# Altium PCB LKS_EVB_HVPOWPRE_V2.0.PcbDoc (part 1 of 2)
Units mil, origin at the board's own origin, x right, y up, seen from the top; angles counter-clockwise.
Board outline 6702.91 x 4340.71 mil, 2 copper layers (Top Layer, Bottom Layer); 149 components, 99 nets, 418 pads, 120 vias.
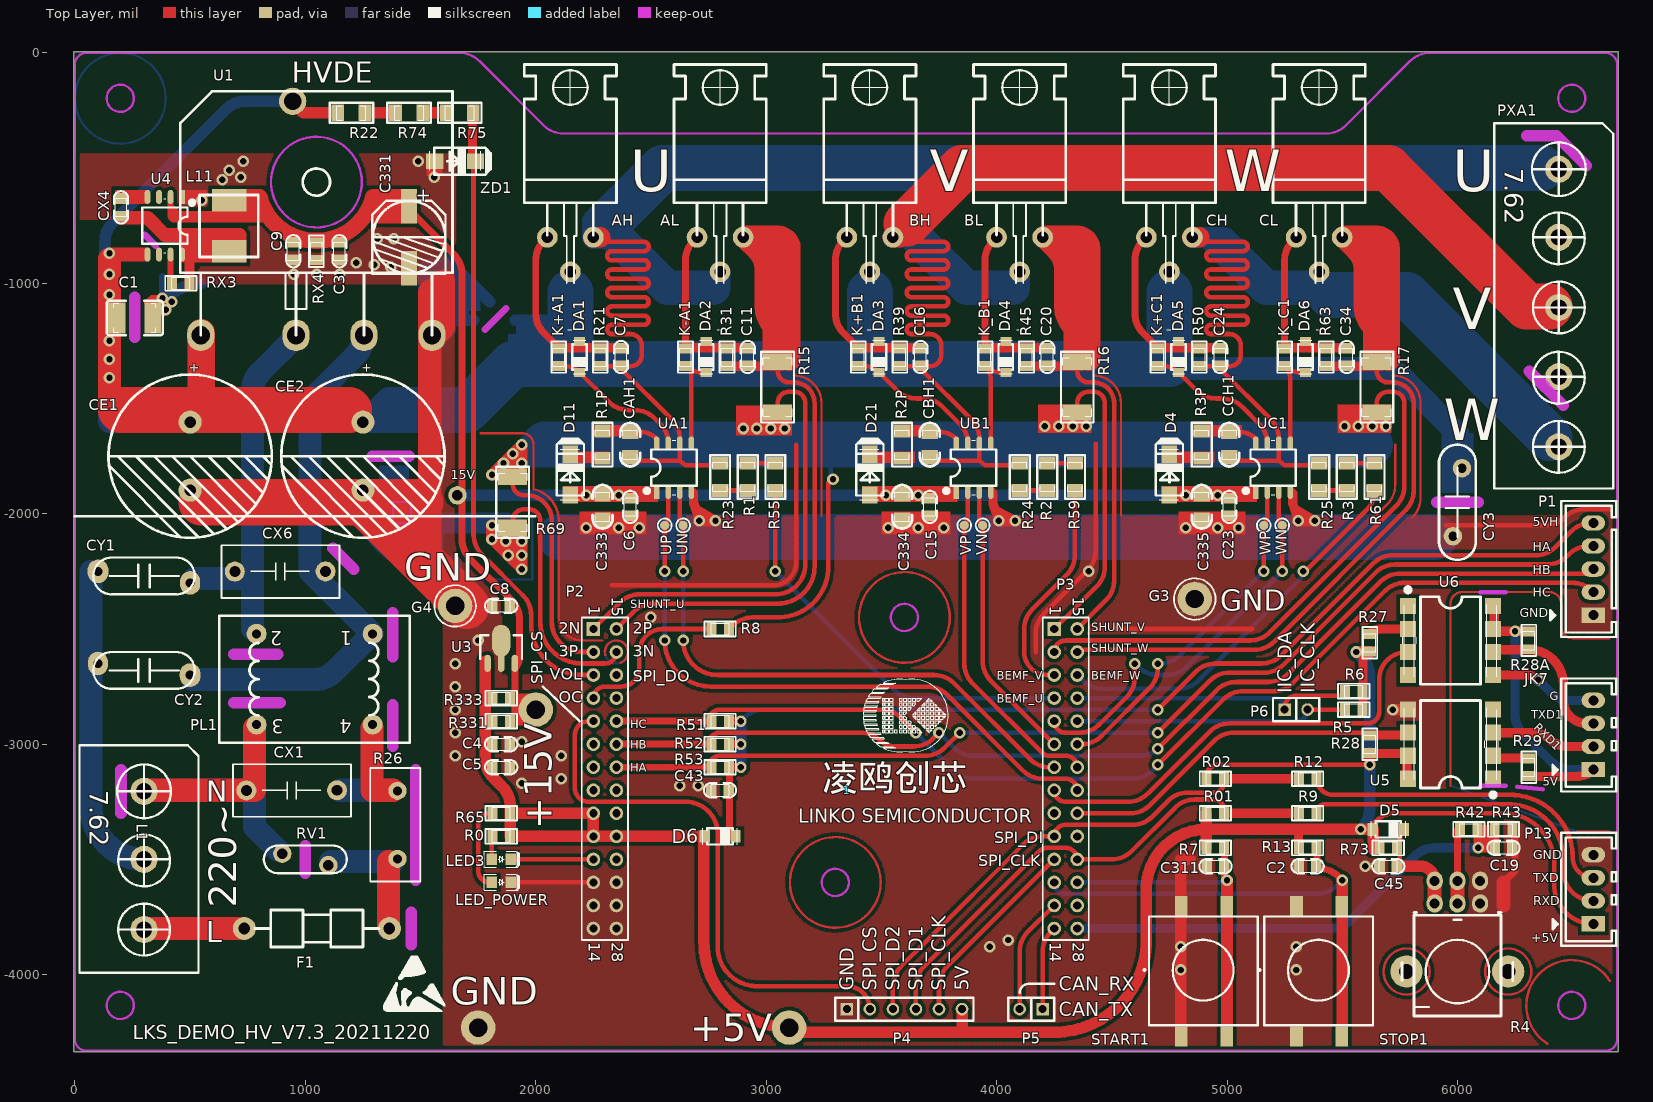
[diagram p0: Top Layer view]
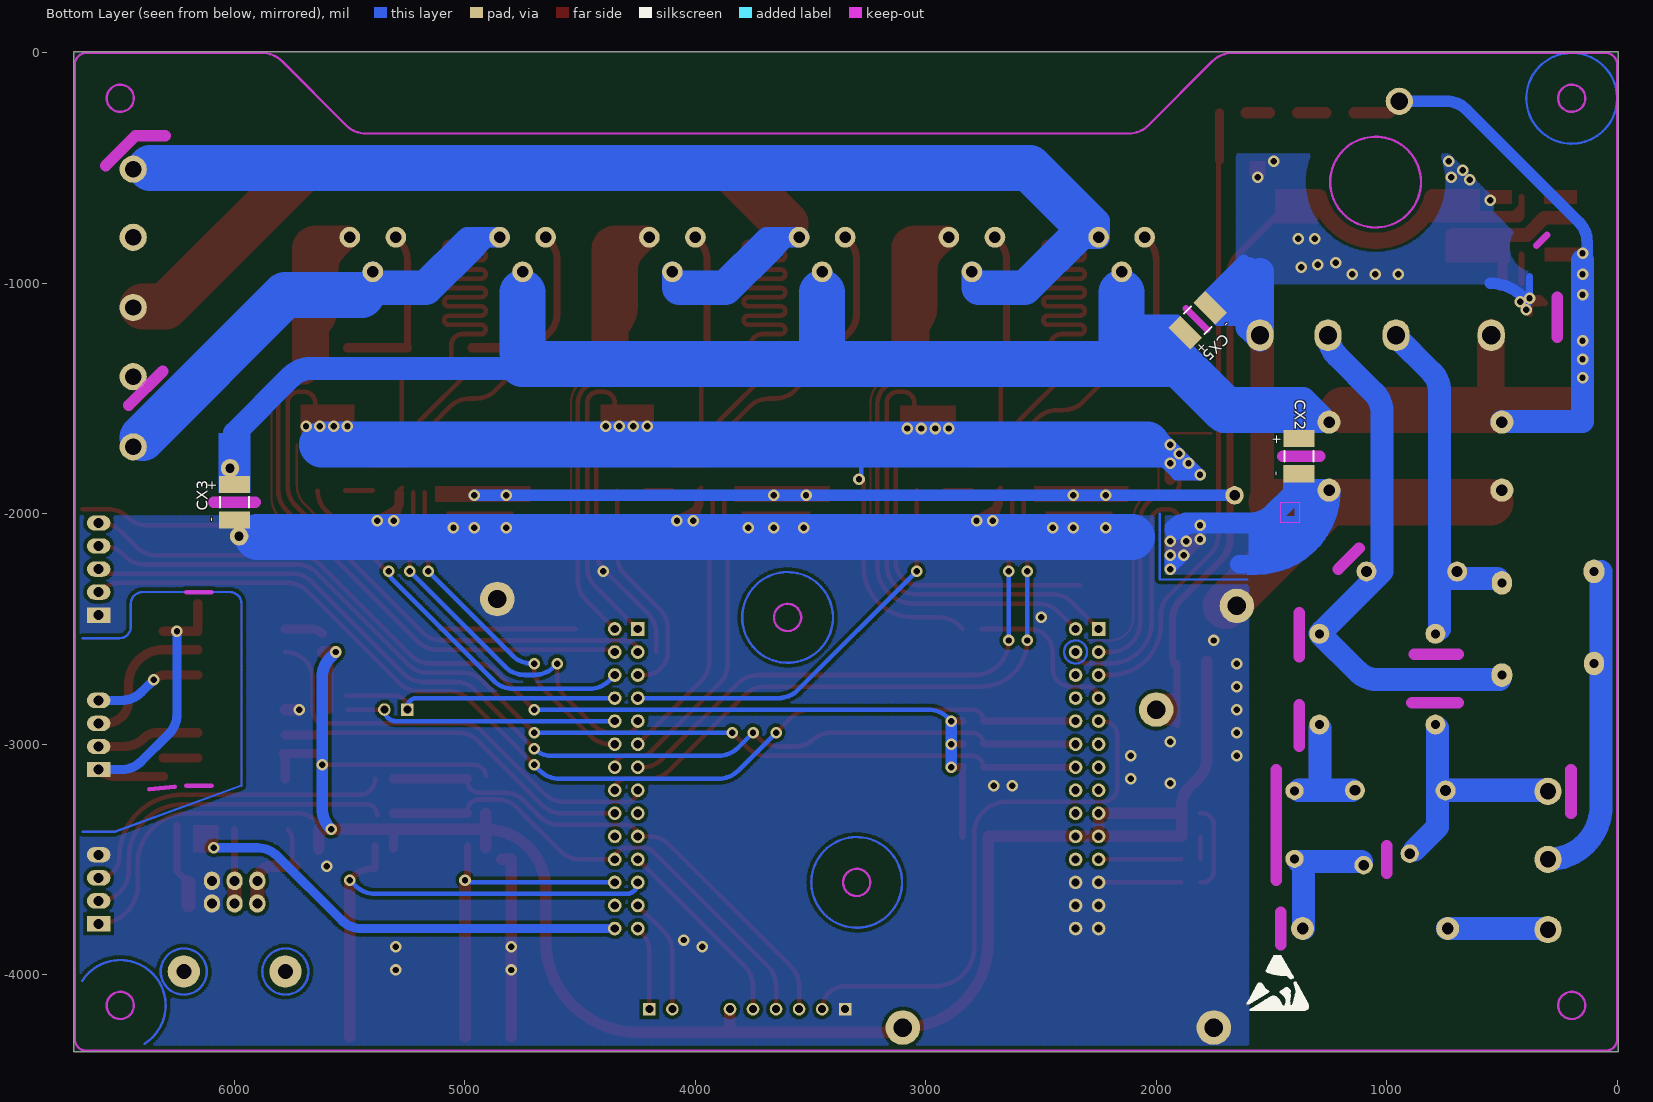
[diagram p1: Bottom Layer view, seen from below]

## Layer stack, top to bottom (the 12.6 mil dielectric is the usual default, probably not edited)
Top Solder: solder mask 0.4, Solder Resist, Dk 3.5
Top Layer: signal copper 1.4
Dielectric1: dielectric 12.6, FR-4, Dk 4.8
Bottom Layer: signal copper 1.4
Bottom Solder: solder mask 0.4, Solder Resist, Dk 3.5

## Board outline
-5,-4335.71 6697.91,-4335.71 6697.91,5 -5,5

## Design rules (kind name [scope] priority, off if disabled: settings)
AssemblyTestPointUsage [All] p0: scope1count=1 scope1_0_kind=Board scope1_0_value=Board scope2count=1 scope2_0_kind=Board scope2_0_value=Board commentlength=0
AssemblyTestpoint [All] p0: scope1count=1 scope1_0_kind=Board scope1_0_value=Board scope2count=1 scope2_0_kind=Board scope2_0_value=Board commentlength=0
Clearance HV铺铜 [All] p0 off: scope1count=1 scope1_0_kind=Board scope1_0_value=Board scope2count=1 scope2_0_kind=Board scope2_0_value=Board commentlength=0 gap=10
Clearance [All] p0 off: scope1count=1 scope1_0_kind=Board scope1_0_value=Board scope2count=1 scope2_0_kind=Board scope2_0_value=Board commentlength=0 gap=10
Clearance 铺铜 [All] p0: scope1count=1 scope1_0_kind=Board scope1_0_value=Board scope2count=1 scope2_0_kind=Board scope2_0_value=Board commentlength=0 gap=15
Clearance 铺铜 [All] p1: gap=15 ignorepadtopadclearanceinfootprint=FALSE
Clearance [All] p2 off: gap=10 ignorepadtopadclearanceinfootprint=FALSE
Clearance HV铺铜 [All] p3 off: gap=10 ignorepadtopadclearanceinfootprint=FALSE
ComponentClearance [All] p0 off: scope1count=1 scope1_0_kind=Board scope1_0_value=Board scope2count=1 scope2_0_kind=Board scope2_0_value=Board commentlength=0 gap=0 collisioncheckmode=3
ComponentClearance [All] p1 off: gap=0 collisioncheckmode=3 verticalgap=10 showdistances=FALSE
DiffPairsRouting [All] p0: scope1count=1 scope1_0_kind=Board scope1_0_value=Board scope2count=1 scope2_0_kind=Board scope2_0_value=Board commentlength=0
FabricationTestPointUsage TestPointUsage [All] p0: scope1count=1 scope1_0_kind=Board scope1_0_value=Board scope2count=1 scope2_0_kind=Board scope2_0_value=Board commentlength=0 valid=0 allowmultiple=FALSE
FabricationTestPointUsage TestPointUsage [All] p1: valid=0 allowmultiple=FALSE
FabricationTestpoint Testpoint [All] p0: scope1count=1 scope1_0_kind=Board scope1_0_value=Board scope2count=1 scope2_0_kind=Board scope2_0_value=Board commentlength=0 side=3 testpointundercomponent=TRUE minsize=40 maxsize=100 preferedsize=60 minholesize=20 maxholesize=40 preferedholesize=32 testpointgrid=1
FabricationTestpoint Testpoint [All] p1: side=3 testpointundercomponent=TRUE minsize=40 maxsize=100 preferedsize=60 minholesize=20 maxholesize=40 preferedholesize=32 testpointgrid=1 allowsidetop=TRUE allowsidebottom=TRUE usegrid=TRUE gridtolerance=0.01
FanoutControl Fanout_BGA [All] p0 off: scope1count=1 scope1_0_kind=Board scope1_0_value=Board scope2count=1 scope2_0_kind=Board scope2_0_value=Board commentlength=69 // Protel DXP Scope 1 Expression Was: IsBGA   Fanout_BGA (Default Rule)
FanoutControl Fanout_LCC [All] p0 off: scope1count=1 scope1_0_kind=Board scope1_0_value=Board scope2count=1 scope2_0_kind=Board scope2_0_value=Board commentlength=69 // Protel DXP Scope 1 Expression Was: IsLCC   Fanout_LCC (Default Rule)
FanoutControl Fanout_SOIC [All] p0 off: scope1count=1 scope1_0_kind=Board scope1_0_value=Board scope2count=1 scope2_0_kind=Board scope2_0_value=Board commentlength=71 // Protel DXP Scope 1 Expression Was: IsSOIC   Fanout_SOIC (Default Rule)
FanoutControl Fanout_Small [All] p0 off: scope1count=1 scope1_0_kind=Board scope1_0_value=Board scope2count=1 scope2_0_kind=Board scope2_0_value=Board commentlength=84 // Protel DXP Scope 1 Expression Was: (CompPinCount < 5)   Fanout_Small (Default Rule)
FanoutControl Fanout_Default [All] p0: scope1count=1 scope1_0_kind=Board scope1_0_value=Board scope2count=1 scope2_0_kind=Board scope2_0_value=Board commentlength=30 // Fanout_Default (Default Rule)
Height [All] p0: scope1count=1 scope1_0_kind=Board scope1_0_value=Board scope2count=1 scope2_0_kind=Board scope2_0_value=Board commentlength=0
HoleSize [All] p0: scope1count=1 scope1_0_kind=Board scope1_0_value=Board scope2count=1 scope2_0_kind=Board scope2_0_value=Board commentlength=0 absolutevalues=TRUE maxlimit=100 minlimit=1 maxpercent=80.000 minpercent=20.000
HoleToHoleClearance [All] p0: scope1count=1 scope1_0_kind=Board scope1_0_value=Board scope2count=1 scope2_0_kind=Board scope2_0_value=Board commentlength=0
LayerPairs [All] p0: scope1count=1 scope1_0_kind=Board scope1_0_value=Board scope2count=1 scope2_0_kind=Board scope2_0_value=Board commentlength=0 enforce=TRUE
MinimumSolderMaskSliver [All] p0: scope1count=1 scope1_0_kind=Board scope1_0_value=Board scope2count=1 scope2_0_kind=Board scope2_0_value=Board commentlength=0
NetAntennae [All] p0: scope1count=1 scope1_0_kind=Board scope1_0_value=Board scope2count=1 scope2_0_kind=Board scope2_0_value=Board commentlength=0
PasteMaskExpansion [All] p0: scope1count=1 scope1_0_kind=Board scope1_0_value=Board scope2count=1 scope2_0_kind=Board scope2_0_value=Board commentlength=0 expansion=0
PlaneClearance [All] p0: scope1count=1 scope1_0_kind=Board scope1_0_value=Board scope2count=1 scope2_0_kind=Board scope2_0_value=Board commentlength=0 clearance=20
PlaneConnect [All] p0: scope1count=1 scope1_0_kind=Board scope1_0_value=Board scope2count=1 scope2_0_kind=Board scope2_0_value=Board commentlength=0 planeconnectstyle=Relief reliefexpansion=20 reliefentries=4 reliefconductorwidth=10 reliefairgap=10
PolygonConnect [All] p0: scope1count=1 scope1_0_kind=Board scope1_0_value=Board scope2count=1 scope2_0_kind=Board scope2_0_value=Board commentlength=0 connectstyle=Direct reliefconductorwidth=30 reliefentries=4 polygonreliefangle="90 Angle"
PolygonConnect [All] p1: connectstyle=Direct reliefconductorwidth=30 reliefentries=4 polygonreliefangle="90 Angle" airgapwidth=10
RoutingCorners [All] p0: scope1count=1 scope1_0_kind=Board scope1_0_value=Board scope2count=1 scope2_0_kind=Board scope2_0_value=Board commentlength=0 cornerstyle=45-Degree minsetback=100 maxsetback=100
RoutingLayers [All] p0: scope1count=1 scope1_0_kind=Board scope1_0_value=Board scope2count=1 scope2_0_kind=Board scope2_0_value=Board commentlength=0 top layer=Horizontal bottom layer=Vertical
RoutingPriority [All] p0: scope1count=1 scope1_0_kind=Board scope1_0_value=Board scope2count=1 scope2_0_kind=Board scope2_0_value=Board commentlength=0
RoutingTopology [All] p0: scope1count=1 scope1_0_kind=Board scope1_0_value=Board scope2count=1 scope2_0_kind=Board scope2_0_value=Board commentlength=0 topology=Shortest
RoutingVias [All] p0: scope1count=1 scope1_0_kind=Board scope1_0_value=Board scope2count=1 scope2_0_kind=Board scope2_0_value=Board commentlength=0 holewidth=28 width=50 viastyle="Through Hole" minholewidth=28 minwidth=50 maxholewidth=28 maxwidth=50
RoutingVias [All] p1: holewidth=28 width=50 viastyle="Through Hole" minholewidth=28 minwidth=50 maxholewidth=28 maxwidth=50
ShortCircuit [All] p0: scope1count=1 scope1_0_kind=Board scope1_0_value=Board scope2count=1 scope2_0_kind=Board scope2_0_value=Board commentlength=0 allowed=FALSE
SilkToBoardRegionClearance [All] p0: scope1count=1 scope1_0_kind=Board scope1_0_value=Board scope2count=1 scope2_0_kind=Board scope2_0_value=Board commentlength=0
SilkToSilkClearance [All] p0: scope1count=1 scope1_0_kind=Board scope1_0_value=Board scope2count=1 scope2_0_kind=Board scope2_0_value=Board commentlength=0
SilkToSolderMaskClearance [All] p0 off: scope1count=1 scope1_0_kind=Board scope1_0_value=Board scope2count=1 scope2_0_kind=Board scope2_0_value=Board commentlength=44 // Protel DXP Scope 1 Expression Was: IsPad
SolderMaskExpansion [All] p0: scope1count=1 scope1_0_kind=Board scope1_0_value=Board scope2count=1 scope2_0_kind=Board scope2_0_value=Board commentlength=0 expansion=3
SolderMaskExpansion [All] p1: expansion=3 istentingtop=FALSE
UnRoutedNet [All] p0: scope1count=1 scope1_0_kind=Board scope1_0_value=Board scope2count=1 scope2_0_kind=Board scope2_0_value=Board commentlength=0
UnpouredPolygon [All] p0: scope1count=1 scope1_0_kind=Board scope1_0_value=Board scope2count=1 scope2_0_kind=Board scope2_0_value=Board commentlength=0
Width [All] p0: scope1count=1 scope1_0_kind=Board scope1_0_value=Board scope2count=1 scope2_0_kind=Board scope2_0_value=Board commentlength=0 maxlimit=300 minlimit=10 preferedwidth=40
Width [All] p1: maxlimit=300 minlimit=10 preferedwidth=40
27 further rules are at their usual default settings.

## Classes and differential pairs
component class LKS_HV_DEMO_081_V4.0: 0 C2 C3 C4 C5 C6 C7 C11 C15 C16 C19 C20 C23 C24 C34 C43 C45 C331 C333 CAH1 CBH1 CCH1 CE1 CE2 CX1 CX2 CX3 CX4 CY1 CY2 D1 D2 D4 D5 D6 D11 D21 DA1 DA2 DA3 DA4 DA5 DA6 F1 G3 G4 JK7 K+A1 K+B1 K+C1 K-A1 K-C1 K_B1 L1 L3 L11 LED1 LED2 LED3 LED_POWER P1 P2 P3 P13 P48V PL1 PXA1 R01 R1 R1P R2 R02 R2P R3 R3P R4 R9 R12 R13 R15 R16 R17 R21 R22 R23 R24 R25 R26 R27 R28 R29 R31 R39 R42 R43 R45 R50 R51 R52 R53 R55 R59 R61 R63 R65 R69 R73 R74 R75 R331 R333 RV1 RX3 RX4 START1 STOP1 U1 U3 U4 U5 U6 UA1 UB1 UC1 UN UP VAH1 VAL1 VBH1 VBL1 VCH1 VCL1 VN VP WN WP

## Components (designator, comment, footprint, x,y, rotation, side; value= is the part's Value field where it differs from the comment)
1 "LKS_sign" LKS_LOGO2 3350,-3200 r0 top
AH "XNF20N60T" TO220-3 2150,-800 r0 top
AL "XNF20N60T" TO220-3 2800,-800 r0 top
BH "XNF20N60T" TO220-3 3450,-800 r0 top
BL "XNF20N60T" TO220-3 4100,-800 r0 top
C1 "100nF/630V" 1812C(4532MM) 260,-1150 r0 top
C2 "100nF/50V" 0805C(2012MM) 5350,-3530 r0 top
C3 "100nF/25V" 0805C(2012MM) 1148.02,-860.53 r90 top
C4 "100nF/50V" 0805C(2012MM) 1850,-3000 r180 top
C5 "10uF/25V" 0805C(2012MM) 1850,-3100 r0 top
C6 "100nF/50V" 0805C(2012MM) 2410,-1970 r90 top
C7 "10nF/50V" 0805C(2012MM) 2370,-1320 r270 top
C8 "100nF/25V" 0805C(2012MM) 1850,-2400 r180 top
C9 "10uF/25V" 0805C(2012MM) 948.02,-860.53 r90 top
C11 "10nF/50V" 0805C(2012MM) 2920,-1320 r270 top
C15 "100nF/50V" 0805C(2012MM) 3710,-1970 r90 top
C16 "10nF/50V" 0805C(2012MM) 3670,-1320 r270 top
C19 "100nF/50V" 0805C(2012MM) 6200,-3450 r180 top
C20 "10nF/50V" 0805C(2012MM) 4220,-1320 r270 top
C23 "100nF/50V" 0805C(2012MM) 5010,-1970 r90 top
C24 "10nF/50V" 0805C(2012MM) 4970,-1320 r270 top
C34 "10nF/50V" 0805C(2012MM) 5520,-1320 r270 top
C43 "100nF/50V" 0805C(2012MM) 2800,-3200 r0 top
C45 "100nF/50V" 0805C(2012MM) 5700,-3530 r0 top
C311 "100nF/50V" 0805C(2012MM) 4950,-3530 r0 top
C331 "220uF/35V" EC-8 1450,-800 r270 top
C333 "10uF/25V" 1206C(3216MM) 2290,-1970 r270 top
C334 "10uF/25V" 1206C(3216MM) 3590,-1970 r270 top
C335 "10uF/25V" 1206C(3216MM) 4890,-1970 r270 top
CAH1 "10uF/25V" 1206C(3216MM) 2410,-1700 r270 top
CBH1 "10uF/25V" 1206C(3216MM) 3710,-1700 r270 top
CCH1 "10uF/25V" 1206C(3216MM) 5010,-1700 r270 top
CE1 "100uF/400V" EC-18 500,-1750 r270 top
CE2 "100uF/400V" EC-18 1250,-1750 r270 top
CH "XNF20N60T" TO220-3 4750,-800 r0 top
CL "XNF20N60T" TO220-3 5400,-800 r0 top
CX1 "100nF/630V" C-X 950,-3200 r0 top
CX2 "0.1uF/1000V" "1812(4532) - POLARIZED" 1380,-1750 r270 bottom
CX3 "0.1uF/1000V" "1812(4532) - POLARIZED" 6000,-1950 r270 bottom
CX4 "1uF/25V" 0805C(2012MM) 200,-670 r270 top
CX5 "0.1uF/1000V" "1812(4532) - POLARIZED" 1820,-1160 r135 bottom
CX6 "100nF/630V" C-X 900,-2250 r0 top
CY1 "222/1KV" C-Y 100,-2250 r180 top
CY2 "222/1KV" C-Y 500,-2700 r0 top
CY3 "222/1KV" "C Y2 103" 6000,-1950 r270 top
D4 "US1J" SMA/DO-214AC 4750,-1830 r90 top
D5 "1N4007" SOD-123 5700,-3370 r0 top
D6 "1N4007" SOD-123 2800,-3400 r0 top
D11 "US1J" SMA/DO-214AC 2150,-1830 r90 top
D21 "US1J" SMA/DO-214AC 3450,-1830 r90 top
DA1 "1N4148（先不焊接）" SOD-123(12) 2190,-1320 r270 top
DA2 "1N4148" SOD-123(12) 2740,-1320 r270 top
DA3 "1N4148（先不焊接）" SOD-123(12) 3490,-1320 r270 top
DA4 "1N4148" SOD-123(12) 4040,-1320 r270 top
DA5 "1N4148（先不焊接）" SOD-123(12) 4790,-1320 r270 top
DA6 "1N4148" SOD-123(12) 5340,-1320 r270 top
F1 "10A/250V" "FUSE 3.6*10" 1050,-3800 r0 top
G3 "PAD1.2" PAD1.2 4860,-2370 r0 top
G4 "PAD1.2" PAD1.2 1650,-2400 r0 top
JK7 "CON4" 2.54-XH-4A-180 6590,-2960 r0 top
K+A1 "10R" 0805R(2012MM) 2100,-1320 r90 top
K+B1 "10R" 0805R(2012MM) 3400,-1320 r90 top
K+C1 "10R" 0805R(2012MM) 4700,-1320 r90 top
K-A1 "10R" 0805R(2012MM) 2650,-1320 r270 top
K_B1 "10R" 0805R(2012MM) 3950,-1320 r270 top
K_C1 "10R" 0805R(2012MM) 5250,-1320 r270 top
L1 "PAD1.2" 栅栏式7.62间距3P 300,-3500 r270 top
L11 "1mH" L-2525CZ 670,-750 r90 top
LED3 "LED" 0805D 1850,-3500 r0 top
LED_POWER "LED_R" 0805D 1850,-3600 r0 top
P1 "Header 5" 2.54-XH-5A-180 6590,-2240 r270 top
P2 "CON14*2" HDR2X14_CEN 2250,-2500 r270 top
P3 "Header 14X2A" HDR2X14_CEN 4250,-2500 r270 top
P4 "SPI" SIP6*2.54 3600,-4150 r0 top
P5 "CAN" SIP2*2.54 4150,-4150 r180 top
P6 "IIC" SIP2*2.54 5300,-2850 r0 top
P13 "CON4" 2.54-XH-4A-180 6590,-3630 r0 top
PL1 "CMC" 立式电感（背面） 900,-2350 r180 top
PXA1 "M4" 栅栏式7.62间距5P 6440,-800 r270 top
R0 "1K" 0805R(2012MM) 1850,-3400 r0 top
R1 "68K/1206" 1206R(3216MM) 2920,-1840 r270 top
R01 "10K" 0805R(2012MM) 4950,-3300 r180 top
R1P "4.7R" 1206R(3216MM) 2290,-1700 r90 top
R2 "68K/1206" 1206R(3216MM) 4220,-1840 r270 top
R02 "10K" 0805R(2012MM) 4950,-3150 r180 top
R2P "4.7R" 1206R(3216MM) 3590,-1700 r90 top
R3 "68K/1206" 1206R(3216MM) 5520,-1840 r270 top
R3P "4.7R" 1206R(3216MM) 4890,-1700 r90 top
R4 "RPot" RK097-W 6000,-3790 r180 top
R5 "10K" 0805R(2012MM) 5550,-2850 r0 top
R6 "10K" 0805R(2012MM) 5550,-2770 r0 top
R7 "10K" 0805R(2012MM) 4950,-3450 r0 top
R8 "1K" 0805R(2012MM) 2800,-2500 r180 top
R9 "10R" 0805R(2012MM) 5350,-3300 r0 top
R12 "10R" 0805R(2012MM) 5350,-3150 r0 top
R13 "10K" 0805R(2012MM) 5350,-3450 r0 top
R15 "100mR" 2512R(6432MM) 3050,-1450 r270 top
R16 "100mR" 2512R(6432MM) 4350,-1450 r270 top
R17 "100mR" 2512R(6432MM) 5650,-1450 r270 top
R21 "20K" 0805R(2012MM) 2280,-1320 r90 top
R22 "68K/1206" 1206R(3216MM) 1200,-260 r0 top
R23 "68K/1206" 1206R(3216MM) 2800,-1840 r90 top
R24 "68K/1206" 1206R(3216MM) 4100,-1840 r90 top
R25 "68K/1206" 1206R(3216MM) 5400,-1840 r90 top
R26 "NTC-5D11" NTC-5D11 1400,-3350 r270 top
R27 "510R" 0805R(2012MM) 5620,-2560 r270 top
R28 "4.7K" 0805R(2012MM) 5620,-3000 r270 top
R28A "4.7K" 0805R(2012MM) 6310,-2550 r90 top
R29 "510R" 0805R(2012MM) 6310,-3100 r90 top
R31 "20K" 0805R(2012MM) 2830,-1320 r270 top
R39 "20K" 0805R(2012MM) 3580,-1320 r90 top
R42 "10K" 0805R(2012MM) 6050,-3370 r0 top
R43 "20K" 0805R(2012MM) 6200,-3370 r180 top
R45 "20K" 0805R(2012MM) 4130,-1320 r270 top
R50 "20K" 0805R(2012MM) 4880,-1320 r90 top
R51 "2K" 0805R(2012MM) 2800,-2900 r0 top
R52 "2K" 0805R(2012MM) 2800,-3000 r0 top
R53 "2K" 0805R(2012MM) 2800,-3100 r0 top
R55 "68K/1206" 1206R(3216MM) 3040,-1840 r90 top
R59 "68K/1206" 1206R(3216MM) 4340,-1840 r90 top
R61 "68K/1206" 1206R(3216MM) 5640,-1840 r90 top
R63 "20K" 0805R(2012MM) 5430,-1320 r270 top
R65 "3.3K" 0805R(2012MM) 1850,-3300 r180 top
R69 "30mR" 2512R(6432MM) 1900,-1950 r270 top
R73 "10K" 0805R(2012MM) 5700,-3450 r0 top
R74 "68K/1206" 1206R(3216MM) 1450,-260 r0 top
R75 "68K/1206" 1206R(3216MM) 1670,-260 r0 top
R331 "0603" 0805R(2012MM) 1850,-2900 r180 top
R333 "0603" 0805R(2012MM) 1850,-2800 r180 top
RV1 "TVR14391" 07D471K 1000,-3500 r0 top
RX3 "0.3" 0805R(2012MM) 460,-1000 r0 top
RX4 "22K" 0805R(2012MM) 1048.02,-860.53 r90 top
START1 "START" "SW-PB  12*12" 4900,-3985 r90 top
STOP1 "STOP" "SW-PB  12*12" 5400,-3985 r90 top
U1 "2510" DB2510 1048.02,-560.53 r0 top
U3 "78L05" SOT-89 1850,-2600 r0 top
U4 "620" SOP8-NCE4614 390,-750 r270 top
U5 "6N137" SOP8(2.54) 5970,-3000 r90 top
U6 "6N137" SOP8(2.54) 5970,-2550 r270 top
UA1 "LKS580" SOIC8(D-1.27) 2600,-1800 r0 top
UB1 "LKS580" SOIC8(D-1.27) 3900,-1800 r0 top
UC1 "LKS580" SOIC8(D-1.27) 5200,-1800 r0 top
UN "TestP" TP-40 2640,-2050 r0 top
UP "TestP" TP-40 2560,-2050 r0 top
VN "TestP" TP-40 3940,-2050 r0 top
VP "TestP" TP-40 3860,-2050 r0 top
WN "TestP" TP-40 5240,-2050 r0 top
WP "TestP" TP-40 5160,-2050 r0 top
ZD1 "5.6V" SMA/DO-214AC 1650,-470 r0 top

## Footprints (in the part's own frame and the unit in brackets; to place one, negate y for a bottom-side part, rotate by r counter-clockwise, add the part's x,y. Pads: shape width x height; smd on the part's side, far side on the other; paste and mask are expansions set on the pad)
2.54-XH-4A-180 [mm]
  rect 2.6x1.7 hole 1.1: 1(0,-3.81)
  oval 2.6x1.7 hole 1.1: 2(0,-1.27) 3(0,1.27) 4(0,3.81)
  silkscreen extent -4.5,-6.22 2.54,6.22
2.54-XH-5A-180 [mm]
  rect 1.7x2.6 hole 1.1: 1(5.08,0)
  oval 1.7x2.6 hole 1.1: 2(2.54,0) 3(0,0) 4(-2.54,0) 5(-5.08,0)
  silkscreen extent -7.49,-4.78 7.49,2.54
07D471K [mil]
  round 80 hole 45: 1(-100,25) 2(100,-25)
  silkscreen extent -180,-60 180,60
0805C(2012MM) [mil]
  rect 46x51.18 smd: 1(-38,0) 2(38,0)
  silkscreen extent -70,-31 70,31
0805D [mil]
  rect 45x50 smd: 1(-41,0) 2(41,0)
  silkscreen extent -74,-35 77,35
0805R(2012MM) [mm]
  rect 1.1x1.5 smd: 1(-0.965,0) 2(0.965,0)
  silkscreen extent -1.73,-0.81 1.73,0.81
1206C(3216MM) [mm]
  rect 1.6x1.8 smd: 1(-1.4,0) 2(1.4,0)
  silkscreen extent -2.4,-1.1 2.4,1.1
1206R(3216MM) [mm]
  rect 1.4x1.8 smd: 1(-1.5,0) 2(1.5,0)
  silkscreen extent -2.4,-1.1 2.4,1.1
"1812(4532) - POLARIZED" [mm]
  rect 1.9x3.4 smd: 1(-1.95,0) 2(1.95,0)
  silkscreen extent -0.58,-1.6 0.58,1.6
1812C(4532MM) [mm]
  rect 1.9x3.4 smd: 1(-2,0) 2(2,0)
  silkscreen extent -3.1,-1.9 3.1,1.9
2512R(6432MM) [mm]
  rect 1.8x3.2 smd: 1(-2.8,0) 2(2.8,0)
  silkscreen extent -3.9,-1.8 3.9,1.8
"C Y2 103" [mil]
  round 80 hole 40: 1(-147.64,19.68) 2(147.64,-19.69)
  silkscreen extent -250,-80 250,80
C-X [mm]
  round 2.2 hole 1.2: 1(-5.232,-0.025) 2(4.768,-0.005)
  silkscreen extent -6.71,-2.93 6.29,2.87
C-Y [mm]
  oval 2.3x2.6 hole 1: 1(0,0)
  oval 2.2x2.6 hole 1: 2(-10.16,1.27)
  silkscreen extent -10.67,-1.52 0.51,2.54
DB2510 [mm]
  oval 3x3.5 hole 2: 1(-2.25,-16.891) 2(-12.75,-16.891) 3(5.25,-16.891) 4(12.75,-16.891)
  silkscreen extent -15,-16.89 15,10
EC-8 [mm]
  rect 3.81x1.8 smd: 1(-3.4,0) 2(3.4,0)
  silkscreen extent -4.01,-4.04 4.01,4.01
EC-18 [mm]
  round 2.54 hole 1.27: 1(-3.75,0) 2(3.75,0)
  silkscreen extent -9,-9 9,9
"FUSE 3.6*10" [mil]
  round 100 hole 50: 1(-315,0) 2(315,0)
  silkscreen extent -270,-80 270,80
HDR2X14_CEN [mm]
  rect 1.5x1.5 hole 0.9: 1(0,0)
  round 1.5 hole 0.9: 2(2.54,0) 3(5.08,0) 4(7.62,0) 5(10.16,0) 6(12.7,0) 7(15.24,0) 8(17.78,0) 9(20.32,0) 10(22.86,0) 11(25.4,0) 12(27.94,0) 13(30.48,0) 14(33.02,0) 15(0,2.54) 16(2.54,2.54) 17(5.08,2.54) 18(7.62,2.54) 19(10.16,2.54) 20(12.7,2.54) 21(15.24,2.54) 22(17.78,2.54) 23(20.32,2.54) 24(22.86,2.54) 25(25.4,2.54) 26(27.94,2.54) 27(30.48,2.54) 28(33.02,2.54)
  silkscreen extent -1.27,-1.27 34.29,3.81
L-2525CZ [mm]
  rect 2.5x3.8 smd: 1(-2.8,0) 2(2.8,0)
  silkscreen extent -3.46,-3.2 3.4,3.27
LKS_LOGO2 [mil]
  silkscreen extent 70,167 440,482
NTC-5D11 [mm]
  round 2 hole 1: 1(-3.75,0) 2(3.75,0)
  silkscreen extent -6.25,-3 6.25,2.5
PAD1.2 [mil]
  round 150 hole 80: 1(0,0)
  silkscreen extent -90,-90 90,90
RK097-W [mm]
  round 3.556 hole 1.651: 0(-5.6,5) 0(5.6,5)
  oval 1.778x2.032 hole 1.1: 1(2.5,-5) 2(-2.5,-5) 3(0,-5) 4(-2.5,-2.5) 5(0,-2.5) 6(2.5,-2.5)
  silkscreen extent -6.1,-1.5 6.1,9.9
SIP2*2.54 [mil]
  rect 55x55 hole 35: 1(-50,0)
  round 55 hole 35: 2(50,0)
  silkscreen extent -100,-50 100,50
SIP6*2.54 [mil]
  rect 55x55 hole 35: 1(-250,0)
  round 55 hole 35: 2(-150,0) 3(-50,0) 4(50,0) 5(150,0) 6(250,0)
  silkscreen extent -300,-50 300,50
SMA/DO-214AC [mm]
  rect 1.9x1.7 smd: A(-2.25,0) K(2.25,0)
  silkscreen extent -2.8,-1.6 3.94,1.6
SOD-123 [mil]
  rect 45x55 smd: 1(-66.93,0) 2(66.93,0)
  silkscreen extent -75,-39 75,39
SOD-123(12) [mm]
  rect 1x1.22 smd: 1(-1.7,0) 2(1.7,0)
  silkscreen extent -1.84,-0.9 1.84,0.9
SOIC8(D-1.27) [mm]
  rect 0.6x1.5 smd: 1(-1.905,-2.7)
  oval 0.6x1.5 smd: 2(-0.635,-2.7) 3(0.635,-2.7) 4(1.905,-2.7) 5(1.905,2.7) 6(0.635,2.7) 7(-0.635,2.7) 8(-1.905,2.7)
  silkscreen extent -3.15,-3 2.5,3
SOP8(2.54) [mil]
  rect 70x70 smd: 1(-150,-185) 2(-50,-185) 3(50,-185) 4(150,-185) 5(150,185) 6(50,185) 7(-50,185) 8(-150,185)
  silkscreen extent -230,-208 190,201
SOP8-NCE4614 [mil]
  rect 60x25 smd: 1(-125,75)
  oval 60x25 smd: 2(-125,25) 3(-125,-25) 4(-125,-75) 5(125,-75) 6(125,-25) 7(125,25) 8(125,75)
  silkscreen extent -118,-98 118,124
SOT-89 [mm]
  oval 0.7x2.1 smd: GND(0,-1.15)
  oval 2x3.5 smd: GND(0,1.25)
  oval 0.7x1.9 smd: IN(1.5,-1.25) OUT(-1.5,-1.25)
  silkscreen extent -2.3,-0.75 2.3,1.85
"SW-PB  12*12" [mm]
  rect 2.2x1.397 smd: 1(-7.2,2.5) 2(-7.2,-2.5) 3(7.2,2.5) 4(7.2,-2.5)
  silkscreen extent -5.98,-5.94 6.02,6.68
TO220-3 [mil]
  round 90 hole 50: 1(-100,0) 2(0,-150) 3(100,0)
  silkscreen extent -200,-400 200,750
TP-40 [mil]
  round 40 smd: 1(-0.39,-0.39)
  silkscreen extent -30,-30 30,30
栅栏式7.62间距3P [mm]
  round 3 hole 1.8: 1(-7.5,0) 2(0,0) 3(7.74,0)
  silkscreen extent -12.58,-7.11 12.5,6
栅栏式7.62间距5P [mm]
  round 3 hole 1.8: 1(-7.5,0) 2(0,0) 3(7.74,0) 4(15.367,0) 5(23.107,0)
  silkscreen extent -12.58,-7.11 27.69,6
立式电感（背面） [mm]
  round 2.2 hole 1: 1(2.834,14.349) 2(2.834,4.349) 3(-9.966,4.349) 4(-9.966,14.349)
  silkscreen extent -14.07,2.35 6.93,16.35

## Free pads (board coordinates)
  round 118.11 hole 75.98: 0(945,-210)
  round 150 hole 80: 0(1750,-4230) 0(3100,-4230) 1(2000,-2850)
  round 80 hole 45: 2(1660,-1920)

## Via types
v1: diameter 50, hole 28, Top Layer to Bottom Layer, 120 vias

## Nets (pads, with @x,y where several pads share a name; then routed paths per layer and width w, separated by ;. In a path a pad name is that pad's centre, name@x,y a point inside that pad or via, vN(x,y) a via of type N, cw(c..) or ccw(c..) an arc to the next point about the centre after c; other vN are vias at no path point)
5V-T: C45.2 D5.2 R4.1 R4.6 R73.2 | length 439.6
  Top Layer w20: C45.2@5750,-3510 5750,-3418.28 cw(c5818.28,-3418.28) D5.2@5770,-3370
  Top Layer w50: C45.2@5740,-3530 5840,-3530 cw(c5840,-3590) R4.1@5900,-3590
  Top Layer w60: R4.6@5900,-3690 R4.1@5900,-3590
5VH: C43.2 D6.2 P1.5 R51.2 R52.2 R53.2 | length 4646.8
  Top Layer w20: v1(4700,-2850) 4864.64,-2685.36 cw(c4950,-2770.71) 4950,-2650 5150,-2650 ccw(c5150,-2529.29) 5235.36,-2614.64 5634.64,-2215.36 cw(c5720,-2300.71) 5720,-2180 6340,-2180 ccw(c6340,-2059.29) 6425.36,-2144.64 6494.64,-2075.36 cw(c6580,-2160.71) 6580,-2040 P1.5@6590,-2040
  Top Layer w30: 2840,-3400 2840,-3200 R53.2@2840,-3100
  Top Layer w35: R53.2@2840,-3100 v1@2880,-3100 ; R52.2@2840,-3000 v1@2880,-3000 ; R51.2@2840,-2900 v1@2880,-2900
  Bottom Layer w20: v1(2890,-2900) 2904.64,-2885.36 cw(c2990,-2970.71) 2990,-2850 v1@4701.72,-2850
  Bottom Layer w50: v1(2890,-3100) v1(2890,-2900)
  other v1: 2890,-3000
+5V: C4.2 C5.1 D5.1 D6.1 P2.9 P2.10 P2.24 P4.6 P13.1 pad.0@3100,-4230 R0.2 R01.2 R02.2 R5.2 R6.2 R7.1 R13.1 R27.2 R28.2 R65.1 R73.1 R331.2 R333.2 U3.OUT U5.7 U5.8 | length 10115.1
  Top Layer w20: R02.2@4910,-3140 cw(c4960,-3140) 4960,-3090 5110,-3090 v1(5620,-3090) ; D5.1@5620,-3360 5644.64,-3335.36 cw(c5730,-3420.71) 5730,-3300 6200,-3300 cw(c6200,-3520) 6420,-3520 6420,-3610 ccw(c6590,-3610) P13.1@6590,-3780
  Top Layer w40: R13.1@5310,-3450 5310,-3370 ; R5.2@5590,-2850 5590,-2600 ; R28.2@5620,-3040 U5.7@5790,-3040 ; U5.8@5780,-3150 U5.7@5780,-3050
  Top Layer w50: U3.OUT@1780,-2640 1780,-3060 ccw(c1900.71,-3060) 1815.36,-3145.36 1854.64,-3184.64 cw(c1769.29,-3270) 1890,-3270 R65.1@1890,-3300 ; P2.10@2250,-3400 P2.9@2250,-3300 R65.1@1890,-3300 ; 2710,-3400 1890,-3400 R65.1@1890,-3300 ; D6.1@2730,-3400 2730,-3860 ccw(c3100,-3860) pad.0@3100,-4230 ; pad.0@3100,-4250 4250,-4250 ccw(c4250,-3850) 4650,-3850 4650,-3630 cw(c4910,-3630) 4910,-3370 ; 3850,-4250 P4.6@3850,-4150 ; R7.1@4910,-3450 R01.2@4910,-3300 ; 4920,-3370 5620,-3370 D5.1@5630,-3370 ; v1(5560,-2600) R27.2@5620,-2600 ; v1(5620,-3090) R28.2@5620,-3040 ; 5635,-3455 D5.1@5635,-3368.28
  Bottom Layer w50: v1(5560,-2600) 5584.64,-2624.64 cw(c5499.29,-2710) 5620,-2710 5620,-3280 cw(c5499.29,-3280) v1@5584.64,-3365.36
  other v1: 5580,-3370
+15V: C3.2 C6.2 C8.1 C9.2 C15.2 C23.2 C331.1 C333.1 C334.1 C335.1 D4.A D11.A D21.A L11.2 pad.1 pad.2 R331.1 R333.1 RX4.2 U3.IN U4.2 UA1.1 UB1.1 UC1.1 | length 6988.6
  Top Layer w25: U4.2@415,-625 415,-665 ; 425,-720 415,-710 415,-665 ; 450,-700 415,-665
  Top Layer w30: C331.1@1450,-680 1644.64,-874.64 cw(c1559.29,-960) 1662.65,-897.65 cw(c1559.29,-960) 1680,-960 1680,-2110 ccw(c1800.71,-2110) 1685.05,-2144.56 ccw(c1800.71,-2110) 1715.36,-2195.36 1894.64,-2374.64 cw(c1809.29,-2460) 1930,-2460 1930,-2621.72 cw(c1861.72,-2621.72) U3.IN@1910,-2670 ; 1910,-2915 U3.IN@1910,-2650
  Top Layer w50: 430,-710 825,-710
  Top Layer w70: 801.23,-624.68 ccw(c1048.02,-560.53) 1294.81,-624.74
  Bottom Layer w50: pad.2@1660,-1920 1990,-1920 ; 1960,-1920 v1(4960,-1920)
  other v1: 2220,-1920 2360,-1920 3520,-1920 3660,-1920 4820,-1920
+310V: AH.2 BH.2 C1.1 CE1.1 CE2.1 CH.2 CX2.1 CX3.1 CX5.1 CY3.1 pad.0@945,-210 R22.1 U1.2 U4.5 | length 10870
  Top Layer w50: pad.0@940,-210 990,-260 R22.1@1140.94,-260
  Top Layer w100: 150,-1530 150,-895
  Top Layer w120: 548.02,-1510.53 U1.2@548.02,-1215.53
  Top Layer w200: 200,-1550 1190,-1550
  Bottom Layer w50: 130,-910 130,-820 cw(c250.71,-820) 165.36,-734.64 654.64,-245.36 cw(c740,-330.71) 740,-210 pad.0@950,-210 ; CX5.1@1910,-1160 2100,-1160
  Bottom Layer w100: 150,-900 150,-1600 CE1.1@500,-1600 ; CE2.1@1280,-1580 1360,-1500 1820,-1500 ; CE2.1@1290,-1600 1710,-1600 ; 4760,-1370 5670,-1370 cw(c5670,-1490.71) 5755.36,-1405.36 6000,-1650
  Bottom Layer w200: 1700,-1550 1900,-1350 2150,-1350 ; 2150,-1040 2150,-1350 ; 3450,-1300 3450,-1040 ; 4750,-1350 2150,-1350 ; 4750,-1300 4750,-1040
  other v1: 150,-1410 150,-1330 150,-1250 150,-1050 150,-960 150,-870
A_N-: DA2.2 K-A1.2 UA1.5 | length 416.7
  Top Layer w20: K-A1.2@2650,-1358 cw(c2650,-1383) 2673.87,-1375.58 cw(c2650,-1383) 2675,-1383 UA1.5@2675,-1693.7 ; K-A1.2@2675,-1376.16 ccw(c2719.84,-1288.16) 2696.91,-1384.23 ccw(c2719.84,-1288.16) 2719.84,-1386.93 DA2.2@2740,-1386.93
A_P+: DA1.2 K+A1.1 UA1.7 | length 622.9
  Top Layer w20: K+A1.1@2100,-1358 2120.16,-1358 cw(c2120.16,-1456.77) DA1.2@2190,-1386.93 2317.72,-1514.64 ccw(c2403.07,-1429.29) 2403.07,-1550 2430,-1550 cw(c2430,-1670.71) 2515.36,-1585.36 2540.56,-1610.56 cw(c2457.43,-1693.7) UA1.7@2575,-1693.7
B_N-: DA4.2 K_B1.2 UB1.5 | length 409.1
  Top Layer w20: K_B1.2@3950,-1358 cw(c3889.64,-1418.36) 3975,-1418.36 UB1.5@3975,-1693.7 ; K_B1.2@3975,-1376.16 ccw(c4019.84,-1288.16) 3996.91,-1384.23 ccw(c4019.84,-1288.16) 4019.84,-1386.93 DA4.2@4040,-1386.93
B_P+: DA3.2 K+B1.1 UB1.7 | length 602.8
  Top Layer w20: K+B1.1@3420.16,-1358 cw(c3420.16,-1456.77) DA3.2@3490,-1386.93 ; DA3.2@3490,-1386.93 3567.72,-1464.64 ccw(c3653.07,-1379.29) 3653.07,-1500 3680,-1500 cw(c3680,-1620.71) 3765.36,-1535.36 3840.62,-1610.62 cw(c3757.59,-1693.63) UB1.7@3875,-1693.63 ; UB1.7@3875,-1693.63 cw(c3757.43,-1693.7) UB1.7@3875,-1693.7 UB1.7@3875,-1693.63
BEMF_U: P3.4 R55.1 | length 1784.8
  Top Layer w20: v1(3040,-2250) R55.1@3040,-1897.86
  Bottom Layer w20: v1(3040,-2250) 3554.64,-2764.64 ccw(c3640,-2679.29) 3640,-2800 P3.4@4250,-2800
BEMF_V: P3.3 R59.1 | length 967.8
  Top Layer w20: P3.3@4250,-2700 4220,-2700 cw(c4220,-2600) 4120,-2600 4120,-2500 cw(c4240.71,-2500) 4155.36,-2414.64 4304.64,-2265.36 ccw(c4219.29,-2180) 4340,-2180 R59.1@4340,-1900
BEMF_W: P3.17 R61.1 | length 1684.4
  Top Layer w20: v1@5340,-2250 5604.64,-1985.36 ccw(c5519.29,-1900) R61.1@5640,-1900
  Bottom Layer w20: P3.17@4350,-2700 4374.64,-2724.64 ccw(c4460,-2639.29) 4460,-2760 4790,-2760 ccw(c4790,-2639.29) 4875.36,-2724.64 5315.86,-2284.14 ccw(c5281.72,-2250) v1(5330,-2250)
C_N-: DA6.2 K_C1.2 UC1.5 | length 409.1
  Top Layer w20: K_C1.2@5250,-1358 cw(c5189.64,-1418.36) 5275,-1418.36 UC1.5@5275,-1693.7 ; K_C1.2@5275,-1376.16 ccw(c5319.84,-1288.16) 5296.91,-1384.23 ccw(c5319.84,-1288.16) 5319.84,-1386.93 DA6.2@5340,-1386.93
C_P+: DA5.2 K+C1.1 UC1.7 | length 602.7
  Top Layer w20: K+C1.1@4720.16,-1358 cw(c4720.16,-1456.77) DA5.2@4790,-1386.93 ; DA5.2@4790,-1386.93 4867.72,-1464.64 ccw(c4953.07,-1379.29) 4953.07,-1500 4980,-1500 cw(c4980,-1620.71) 5065.36,-1535.36 5140.61,-1610.61 cw(c5057.43,-1693.7) UC1.7@5175,-1693.7
C_RXD: JK7.2 U5.3 | length 446
  Top Layer w40: U5.3@6160,-2950 6335.15,-2950 cw(c6335.15,-3034.14) 6394.64,-2974.64 ccw(c6480,-2889.29) 6480,-3010 JK7.2@6590,-3010
C_TXD: JK7.3 R28A.1 U6.6 | length 612.7
  Top Layer w40: U6.6@6160,-2590 6310,-2590 cw(c6310,-2740) 6460,-2740 6460,-2810 ccw(c6560,-2810) JK7.3@6560,-2910
CAN_RX: P3.13 P5.2 | length 506.9
  Top Layer w20: P5.2@4100,-4150 4100,-3900 cw(c4220.71,-3900) 4135.36,-3814.64 P3.13@4250,-3700
CAN_TX: P3.14 P5.1 | length 365.5
  Top Layer w20: P5.1@4200,-4150 4200,-3900 cw(c4320.71,-3900) 4235.36,-3814.64 P3.14@4250,-3800
GND: C1.2 C2.1 C3.1 C4.1 C5.2 C6.1 C8.2 C9.1 C15.1 C19.1 C23.1 C43.1 C45.1 C311.1 C331.2 C333.2 C334.2 C335.2 CE1.2 CE2.2 CX2.2 CX3.2 CX5.2 CY3.2 G3.1 G4.1 LED_POWER.2 P1.1 P2.12 P2.13 P2.14 P2.16 P2.26 P2.27 P2.28 P4.1 P13.4 pad.0@1750,-4230 R4.2 R4.4 R43.1 R69.2 RX4.1 START1.1 START1.3 STOP1.1 STOP1.3 U1.4 U3.GND U4.1 U5.5 UA1.4 UB1.4 UC1.4 ZD1.A | length 23066.6
  Top Layer w10: 1760,-1650 1940,-1650 cw(c1940,-1700) 1990,-1700 1990,-1890 ; 1991.48,-1893.59 cw(c1960,-2030) 2100,-2030 2100,-2450 ccw(c2200,-2450) 2200,-2550 2290,-2550 ; 3120,-1400 cw(c3120,-1520) 3240,-1520 3240,-2010 ; 4420,-1400 cw(c4420,-1520) 4540,-1520 4540,-2010 ; 5630,-2025 5694.64,-1960.36 ccw(c5609.29,-1875) 5730,-1875 5730,-1699.14 ; 5720,-1400 cw(c5720,-1520) 5840,-1520 5840,-1930 cw(c5719.29,-1930) 5804.64,-2015.36
  Top Layer w20: LED_POWER.2@1891,-3600 P2.12@2250,-3600 ; R69.2@1900,-2060 1900,-2030 cw(c1950,-2030) 1950,-1980 1970,-1980 cw(c1970,-2030) 2020,-2030 2020,-2470 ccw(c2200,-2470) 2200,-2650 2300,-2650 ccw(c2300,-2600) P2.16@2350,-2600 ; 2330,-2310 3030,-2310 ccw(c3030,-2210) 3130,-2210 ; 2675,-1955 UA1.4@2675,-1906.3 ; UA1.4@2675,-1887 2695,-1907 2695,-1952 ; 3130,-2220 3130,-1700 ; 3975,-1955 UB1.4@3975,-1906.3 ; UB1.4@3975,-1887 3995,-1907 3995,-1952 ; 4170,-2600 4170,-2520 cw(c4290.71,-2520) 4205.36,-2434.64 4394.64,-2245.36 ccw(c4309.29,-2160) 4430,-2160 4430,-1695.91 ; 4520,-2500 5110,-2500 ; 5275,-1955 UC1.4@5275,-1906.3 ; UC1.4@5275,-1887 5295,-1907 5295,-1952 ; 5950,-2050 6380,-2050 ccw(c6380,-1929.29) 6465.36,-2014.64 cw(c6549,-2098.28) 6528.15,-1981.85 cw(c6549,-2098.28) 6549,-1980 6660,-1980
  Top Layer w30: C1.2@315,-1085 335,-1065 v1(380,-1065) 395,-1080 395,-1085 ; C1.2@335,-1085 395,-1085 ; v1@380,-1130 v1@380,-1125 ; 380,-1090 v1@380,-1125 ; v1(395,-1115) v1@395,-1110 ; 6200,-3600 6250,-3550 6250,-3450 R43.1@6250,-3350 ; v1@380,-1125 v1@395,-1110 ; v1@395,-1110 395,-1085 ; v1@395,-1110 420,-1085 395,-1085
  Top Layer w40: 2685,-1950 v1(2710,-2030) ; 2695,-1980 v1(2780,-2030) ; 3985,-1955 v1(4010,-2030) ; 3995,-1985 v1(4080,-2030) ; 5285,-1955 v1(5310,-2030) ; 5295,-1980 5327.99,-1999.41 v1(5380,-2030)
  Top Layer w50: v1(2710,-2030) v1(2780,-2030) ; v1(4010,-2030) v1(4080,-2030) ; START1.1@4800,-4270 v1(4800,-3980) v1(4800,-3880) 4800,-3500 4840,-3500 ; v1(5310,-2030) v1(5380,-2030) ; v1(5720,-2850) U5.5@5780,-2850 ; v1(1810,-2110) v1(1940,-2240) 1940,-2050 v1(1810,-2050) v1(1810,-2110)
  Top Layer w60: 6200,-3700 6200,-3600
  Top Layer w100: 1540,-2140 U1.4@1540,-1220 ; U1.4@1550,-1240 1600,-1190 1600,-990
  Top Layer w120: U1.4@1550,-1220 1550,-1040
  Top Layer w200: 550,-1950 1250,-1950 1464.64,-2164.64 ; 1220,-1950 1500,-1950 ; 1460,-2160 G4.1@1700,-2400
  Bottom Layer w10: CE2.2@1205,-1900 ccw(c1565,-1900) 1565,-2260 1600,-2260 ; CE2.2@1250,-1855 1355,-1855 cw(c1355,-1975.71) 1440.36,-1890.36 1514.64,-1964.64 ccw(c1600,-1879.29) 1600,-2000 ; 1598.28,-2000 1860,-2000 cw(c1860,-2120.71) 1945.36,-2035.36 1960,-2050
  Bottom Layer w30: v1@380,-1070 380,-970 ; v1@390,-1070 390,-1110 v1(420,-1080)
  Bottom Layer w50: v1@391.48,-1078.06 cw(c550,-1200) 550,-1000 ; 1600,-1160 CX5.2@1730,-1160 ; 1620,-900 CX5.2@1800,-1080 ; v1(1880,-2180) v1(1940,-2240) v1(1940,-2180)
  Bottom Layer w80: CE2.2@1250,-1900 ccw(c1570,-1900) 1570,-2220 1640,-2220
  Bottom Layer w90: CE2.2@1250,-1900 1340,-1900 cw(c1340,-2020.71) 1425.36,-1935.36 ; 1420,-1930 1504.64,-2014.64 ; 1494.64,-2004.64 ccw(c1580,-1919.29) 1580,-2040 ; 1590,-2040 1871.72,-2040 ; 1871.72,-2050 cw(c1871.72,-2118.28) 1920,-2070
  Bottom Layer w110: U1.4@1550,-1240 1600,-1190 1600,-940
  Bottom Layer w120: U1.4@1550,-1220 1550,-950
  Bottom Layer w200: 2105,-2100 5310,-2100 5900,-2100
  other v1: 5300,-3980 3970,-3880 5300,-3880 4050,-3850 5600,-3530 2625,-3180 2705,-3180 1940,-3170 2110,-3150 1650,-3050 2110,-3050 1940,-2990 1650,-2950 1650,-2850 1650,-2750 1650,-2650 1750,-2550 2500,-2450 4400,-2250 1870,-2120 1940,-2120 2220,-2060 2360,-2060 2450,-2060 3530,-2060 3660,-2060 3770,-2060 4820,-2060 4960,-2060 5050,-2060 950,-960 1050,-960 1150,-960 1370,-930 1300,-920 1220,-910 1313.02,-805.53 1383.02,-805.53 550,-640 640,-550 720,-540 1560,-540 670,-510 730,-470 1490,-470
